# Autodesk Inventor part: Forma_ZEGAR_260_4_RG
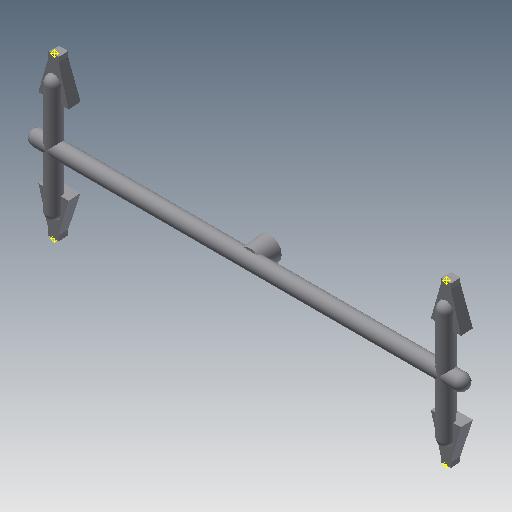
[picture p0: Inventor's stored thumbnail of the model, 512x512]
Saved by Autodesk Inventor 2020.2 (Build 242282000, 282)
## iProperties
Created: 2015-01
Part Number: Forma_ZEGAR_260_4_RG
Material: Ogólny
Document SubType Name: Modeling
Designer: F.Stasiak
Density: 1 g/cm^3
Appearance: Domyślna
Catalog Web Link: www.expertbooks.pl
Manager: www.cadconsulting.pl
Company: Fabian Stasiak CAD Consulting
Author: F.Stasiak
Subject: Zbiór ćwiczeń. Autodesk Inventor 2020. Kurs Professional
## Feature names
1. Wyciągnięcie proste7 [Extrusion]
2. Przeciągnięcie1
3. Obrót1 [Revolution]
4. Wyciągnięcie proste1 [Extrusion]
5. Przeciągnięcie2
6. Obrót2 [Revolution]
7. Wyciągnięcie proste2 [Extrusion]
8. Przeciągnięcie3
9. Obrót3 [Revolution]
10. Wyciągnięcie proste3 [Extrusion]
11. Przeciągnięcie4
12. Obrót4 [Revolution]
13. Wyciągnięcie proste4 [Extrusion]
14. Przeciągnięcie5
15. Obrót5 [Revolution]
16. Wyciągnięcie proste5 [Extrusion]
17. Przeciągnięcie6
18. Obrót6 [Revolution]
19. Wyciągnięcie proste6 [Extrusion]
20. Wyciągnięcie złożone1
21. Wyciągnięcie złożone2
22. Wyciągnięcie złożone3
23. Wyciągnięcie złożone4
## Parameters: d0 = -9.8085 mm, d1 = 39 mm, d2 = 8 mm, d3 = 3 mm, d4 = 0, d5 = 0, d6 = -3 mm, d7 = 3 mm, d8 = 180 deg, d9 = 3 mm, d10 = 3 mm, d11 = 0, d12 = 3 mm, d13 = 0, d14 = 0, d15 = -3 mm, d16 = 3 mm, d17 = 180 deg, d18 = 3 mm, d19 = 3 mm, d20 = 0, d21 = 3 mm, d22 = 0, d23 = 0, d24 = 3 mm, d25 = 3 mm, d26 = 180 deg, d27 = 3 mm, d28 = 3 mm, d29 = 0, d30 = 3 mm, d31 = 0, d32 = 0, d33 = 3 mm, d34 = 3 mm, d35 = 180 deg, d36 = 3 mm, d37 = 3 mm, d38 = 0, d39 = 3 mm, d40 = 0, d41 = 0, d42 = 3 mm, d43 = 3 mm, d44 = 180 deg, d45 = 3 mm, d46 = 3 mm, d47 = 0, d48 = 3 mm, d49 = 0, d50 = 0, d51 = 3 mm, d52 = 3 mm, d53 = 180 deg, d54 = 3 mm, d55 = 3 mm, d56 = 0, d57 = 1 mm, d58 = 2 mm, d59 = 2 mm, d60 = 87 deg, d61 = 87 deg, d62 = 6 mm, d63 = 2.5 mm, d64 = 87 deg, d65 = 87 deg, d66 = 0, d67 = 90 deg, d68 = 0, d69 = 90 deg, d70 = 1 mm, d71 = 1 mm, d72 = 2 mm, d73 = 2 mm, d74 = 87 deg, d75 = 87 deg, d76 = 6 mm, d77 = 2.5 mm, d78 = 87 deg, d79 = 87 deg, d80 = 0, d81 = 90 deg, d82 = 0, d83 = 90 deg, d84 = 1 mm, d85 = 1 mm, d86 = 2 mm, d87 = 2 mm, d88 = 87 deg, d89 = 87 deg, d90 = 6 mm, d91 = 2.5 mm, d92 = 87 deg, d93 = 87 deg, d94 = 0, d95 = 90 deg, d96 = 0, d97 = 90 deg, d98 = 1 mm, d99 = 1 mm, d100 = 2 mm, d101 = 2 mm, d102 = 87 deg, d103 = 87 deg, d104 = 6 mm, d105 = 2.5 mm, d106 = 87 deg, d107 = 87 deg, d108 = 0, d109 = 90 deg, d110 = 0, d111 = 90 deg, d112 = 1 mm, d113 = 4 mm, d114 = 5 deg
